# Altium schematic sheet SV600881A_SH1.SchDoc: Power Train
size 431 x 279 mm; Date: Not shown in title block; ApprovedBy: Not shown in title block; CheckedBy: Not shown in title block; Author: Not shown in title block; CompanyName: Not shown in title block; DrawnBy: KNielson; Engineer: Eric Lee; Organization: SVA PPD; Address1: Not shown in title block; Address2: Not shown in title block; Address3: Not shown in title block; Address4: Not shown in title block; DocumentNumber: 3; Revision: E1; SheetNumber: 3; SheetTotal: 4; PageSetup: Record=PageOptions|CenterHorizontal=True|CenterVertical=True|PrintScale=1.09|XCorrection=1.00|YCorrection=1.00|PrintKind=0|BorderSize=5000000|LeftOffset=0|BottomOffset=0|Orientation=2|PaperLength=1000|PaperWidth=1000|Scale=100|PaperSource=7|PrintQuality=600|MediaType=1|DitherType=10|PaperKind=11" x 17"|PrintScaleMode=1
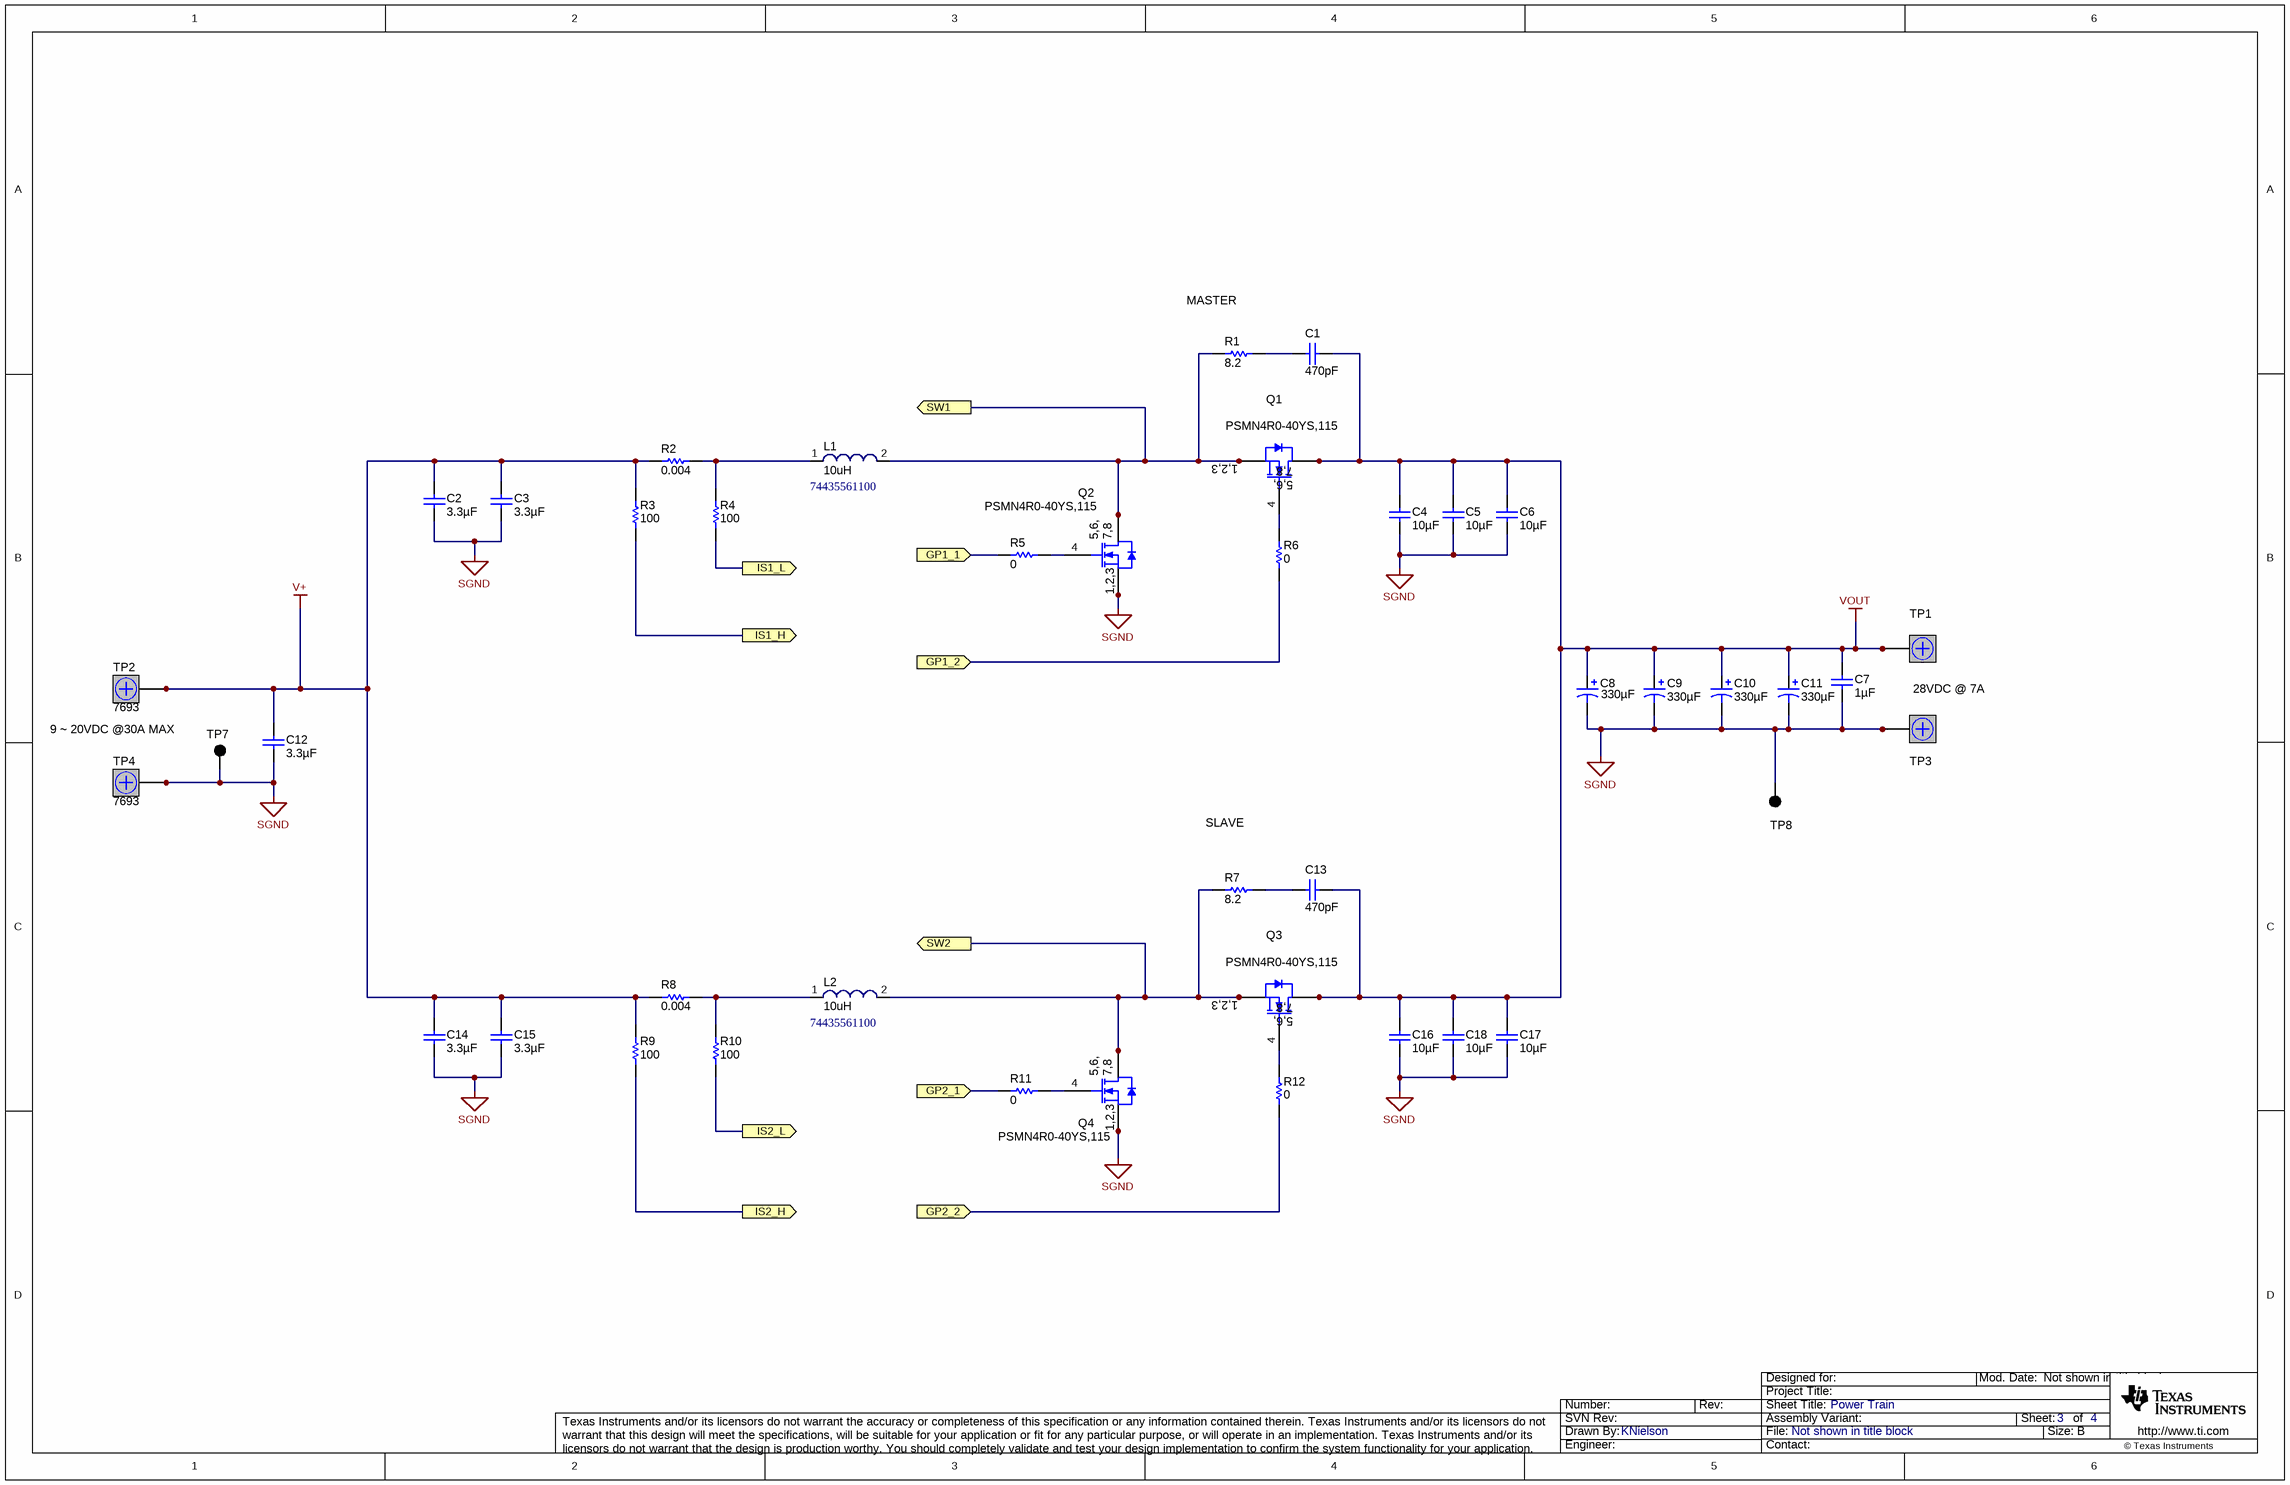
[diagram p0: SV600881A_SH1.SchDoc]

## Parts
C1  ValueDisplayed: 470pF  [0805_HV]  (hidden comment: GRM2165C2A471JA01D)
C2  3.3µF  [1206]
C3  3.3µF  [1206]
C4  10µF  [1206]
C5  10µF  [1206]
C6  10µF  [1206]
C7  ValueDisplayed: 1µF  [0805_HV]  (hidden comment: GRM21BR71H105KA12L)
C8  ValueDisplayed: 330µF  [SM_RADIAL_G]  (hidden comment: EEE-FP1V331AP)
C9  ValueDisplayed: 330µF  [SM_RADIAL_G]  (hidden comment: EEE-FP1V331AP)
C10  ValueDisplayed: 330µF  [SM_RADIAL_G]  (hidden comment: EEE-FP1V331AP)
C11  ValueDisplayed: 330µF  [SM_RADIAL_G]  (hidden comment: EEE-FP1V331AP)
C12  3.3µF  [1206]
C13  ValueDisplayed: 470pF  [0805_HV]  (hidden comment: GRM2165C2A471JA01D)
C14  3.3µF  [1206]
C15  3.3µF  [1206]
C16  10µF  [1206]
C17  10µF  [1206]
C18  10µF  [1206]
L1  10uH  PartNumber: 74435561100  [WE-HCI 1890]
L2  10uH  PartNumber: 74435561100  [WE-HCI 1890]
Q1  PSMN4R0-40YS,115  [PG-TDSON-8]
Q2  PSMN4R0-40YS,115  [PG-TDSON-8]
Q3  PSMN4R0-40YS,115  [PG-TDSON-8]
Q4  PSMN4R0-40YS,115  [PG-TDSON-8]
R1  8.2  [2010]
R2  0.004  [KRL7638]
R3  value 100  [0603_HV]  (hidden comment: CRCW0603100RFKEA)
R4  value 100  [0603_HV]  (hidden comment: CRCW0603100RFKEA)
R5  value 0  [0603_HV]  (hidden comment: ERJ-3GEY0R00V)
R6  value 0  [0603_HV]  (hidden comment: ERJ-3GEY0R00V)
R7  8.2  [2010]
R8  0.004  [KRL7638]
R9  value 100  [0603_HV]  (hidden comment: CRCW0603100RFKEA)
R10  value 100  [0603_HV]  (hidden comment: CRCW0603100RFKEA)
R11  value 0  [0603_HV]  (hidden comment: ERJ-3GEY0R00V)
R12  value 0  [0603_HV]  (hidden comment: ERJ-3GEY0R00V)
TP1  7693  [7693]  (value not drawn)
TP2  7693  [7693]
TP3  7693  [7693]  (value not drawn)
TP4  7693  [7693]
TP7  5011  [Keystone5011]  (value not drawn)
TP8  5011  [Keystone5011]  (value not drawn)

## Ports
GP1_1, GP1_2, GP2_1, GP2_2, IS1_H, IS1_L, IS2_H, IS2_L, SW1, SW2

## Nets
SGND: C2.2 C3.2 C4.2 C5.2 C6.2 C7.2 C8.2(-) C9.2(-) C10.2(-) C11.2(-) C12.2 C14.2 C15.2 C16.2 C17.2 C18.2 Q2.1(S) Q2.2(S) Q2.3(S) Q4.1(S) Q4.2(S) Q4.3(S) TP3.1 TP3.2 TP3.3 TP3.4 TP4.1 TP4.2 TP4.3 TP4.4 TP7.1 TP8.1
V+: C2.1 C3.1 C12.1 C14.1 C15.1 R2.1 R3.2 R8.1 R9.2 TP2.1 TP2.2 TP2.3 TP2.4
VOUT: C1.1 C4.1 C5.1 C6.1 C7.1 C8.1(+) C9.1(+) C10.1(+) C11.1(+) C13.1 C16.1 C17.1 C18.1 Q1.5(D) Q1.6(D) Q1.7(D) Q1.8(D) Q1.9(D) Q3.5(D) Q3.6(D) Q3.7(D) Q3.8(D) Q3.9(D) TP1.1 TP1.2 TP1.3 TP1.4
GP1_1: R5.2 ; port GP1_1
GP1_2: R6.1 ; port GP1_2
GP2_1: R11.1 ; port GP2_1
GP2_2: R12.2 ; port GP2_2
IS1_H: R3.1 ; port IS1_H
IS1_L: R4.1 ; port IS1_L
IS2_H: R9.1 ; port IS2_H
IS2_L: R10.1 ; port IS2_L
SW1: L1.2 Q1.1(S) Q1.2(S) Q1.3(S) Q2.5(D) Q2.6(D) Q2.7(D) Q2.8(D) Q2.9(D) R1.1 ; port SW1
SW2: L2.2 Q3.1(S) Q3.2(S) Q3.3(S) Q4.5(D) Q4.6(D) Q4.7(D) Q4.8(D) Q4.9(D) R7.1 ; port SW2
NetC1_2: C1.2 R1.2
NetC13_2: C13.2 R7.2
NetL1_1: L1.1 R2.2 R4.2
NetL2_1: L2.1 R8.2 R10.2
NetQ1_4: Q1.4(G) R6.2
NetQ2_4: Q2.4(G) R5.1
NetQ3_4: Q3.4(G) R12.1
NetQ4_4: Q4.4(G) R11.2

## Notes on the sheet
- (near R1) MASTER
- 28VDC @ 7A
- 9 ~ 20VDC @30A MAX
- SLAVE

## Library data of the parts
C1 C13 = GRM2165C2A471JA01D: CAP, CERM, 470pF, 100V, +/-5%, C0G/NP0, 0805; Manufacturer: MuRata; Polarized: N; CompType: Capacitor; U/M: EA; Cap_F: 0.00000000047; Tolerance_%: 5; VDC_V: 100; TaMin_C: -55; TaMax_C: 125; Cap_Case: 0805
C2 C3 C12 C14 C15 = C3216X7R1H335K160AC: CAP CER 3.3UF 50V 10% X7R 1206; Manufacturer: TDK Corporation; CompType: Used in some BOM reports.  Useful for finding later.; SymbolVersion: use current date i.e. 2008-05-20; U/M: EA, IN, or GM; SymbolCreator: Use LDAP id
C4-C6 C16-C18 = GMK316AB7106KL-TR: CAP CER 10UF 35V 10% X7R 1206; Manufacturer: Taiyo Yuden; CompType: Used in some BOM reports.  Useful for finding later.; SymbolVersion: use current date i.e. 2008-05-20; U/M: EA, IN, or GM; SymbolCreator: Use LDAP id
C7 = GRM21BR71H105KA12L: CAP, CERM, 1uF, 50V, +/-10%, X7R, 0805; Manufacturer: MuRata; Polarized: N; CompType: Capacitor; U/M: EA; Cap_F: 0.000001; Tolerance_%: 10; VDC_V: 50; TaMin_C: -55; TaMax_C: 125; Cap_Case: 0805
C8-C11 = EEE-FP1V331AP: CAP ALUM 330UF 35V 20% SMD; Manufacturer: Panasonic; Polarized: Y; CompType: Capacitor; U/M: EA; Cap_F: 0.00033; Tolerance_%: 20; Value1: 0.06 ohm; VDC_V: 35; ESR_Ohm: 0.06; IRMS_A: 1.19; TaMin_C: -55; TaMax_C: 105; Cap_Case: G
L1 L2 = WE-HCI 1890, 74435561100: SMD Flat Wire High Current Inductor WE-HCI, L=10.0 µH; Inductance: 10.0 µH
Q1-Q4 = PSMN4R0-40YS,115: MOSFET N-CH 40V 100A LFPAK; Manufacturer: NXP Semiconductors; SymbolVersion: use current date i.e. 2008-05-20; SymbolCreator: Use LDAP id; CompType: Used in some BOM reports.  Useful for finding later.; U/M: EA, IN, or GM; Input Capacitance (Ciss) @ Vds: 2410pF @ 20V; Vgs(th) (Max) @ Id: 4V @ 1mA; Rds On (Max) @ Id, Vgs: 4.2 mOhm @ 15A, 10V; Gate Charge (Qg) @ Vgs: 38nC @ 10V; FET Type: MOSFET N-Channel, Metal Oxide; FET Feature: Standard; Power - Max: 106W
R1 R7 = CRCW20108R20JNEF: RES 8.2 OHM 3/4W 5% 2010 SMD; Manufacturer: Vishay Dale; CompType: Used in some BOM reports.  Useful for finding later.; SymbolVersion: use current date i.e. 2008-05-20; Power_W: 0.75W, 3/4W; TempCo: ±200ppm/°C; U/M: EA, IN, or GM; SymbolCreator: Use LDAP id
R2 R8 = KRL7638-C-R004: RES, 0.004 OHM, 3W, 1%, 3015, WIDE; PartNumber: KRL7638-C-R004-F-T1; Manufacturer: Susumu; Alternate PartNumber: FCSL76R004FER; Alternate Manufacturer: Ohmite; U/M: EA, IN, or GM; SymbolCreator: bkinsc; Description: RES 0.004 OHM 3W 1% 3015 WIDE; TempCo: ±50ppm/°C
R3 R4 R9 R10 = CRCW0603100RFKEA: RES, 100 ohm, 1%, 0.1W, 0603; Manufacturer: Vishay-Dale; Alternate PartNumber: Equivalent; Alternate Manufacturer: Any; CompType: Resistor; Value_Code: 100R; Tolerance_%: 1; Power_W: 0.1; VDC_V: 75; TempCo: 100 ppm/C; EIA_Code: E96; U/M: EA
R5 R6 R11 R12 = ERJ-3GEY0R00V: RES, 0 ohm, 5%, 0.1W, 0603; Manufacturer: Panasonic; CompType: Resistor; Value_Code: 0000; Tolerance_%: 5; Power_W: 0.1; VDC_V: 50; TempCo: 600 ppm/C; EIA_Code: E24; U/M: EA
TP1-TP4 = 7693: Terminal screw, vertical, snap-in; Manufacturer: Keystone; CompType: Screw Terminal; U/M: EA; Value: 15A; SymbolCreator: codlsc
TP7 TP8 = 5011: Test Point, TH, Multipurpose, Black; Manufacturer: Keystone; CompType: Test Point Loop; U/M: EA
